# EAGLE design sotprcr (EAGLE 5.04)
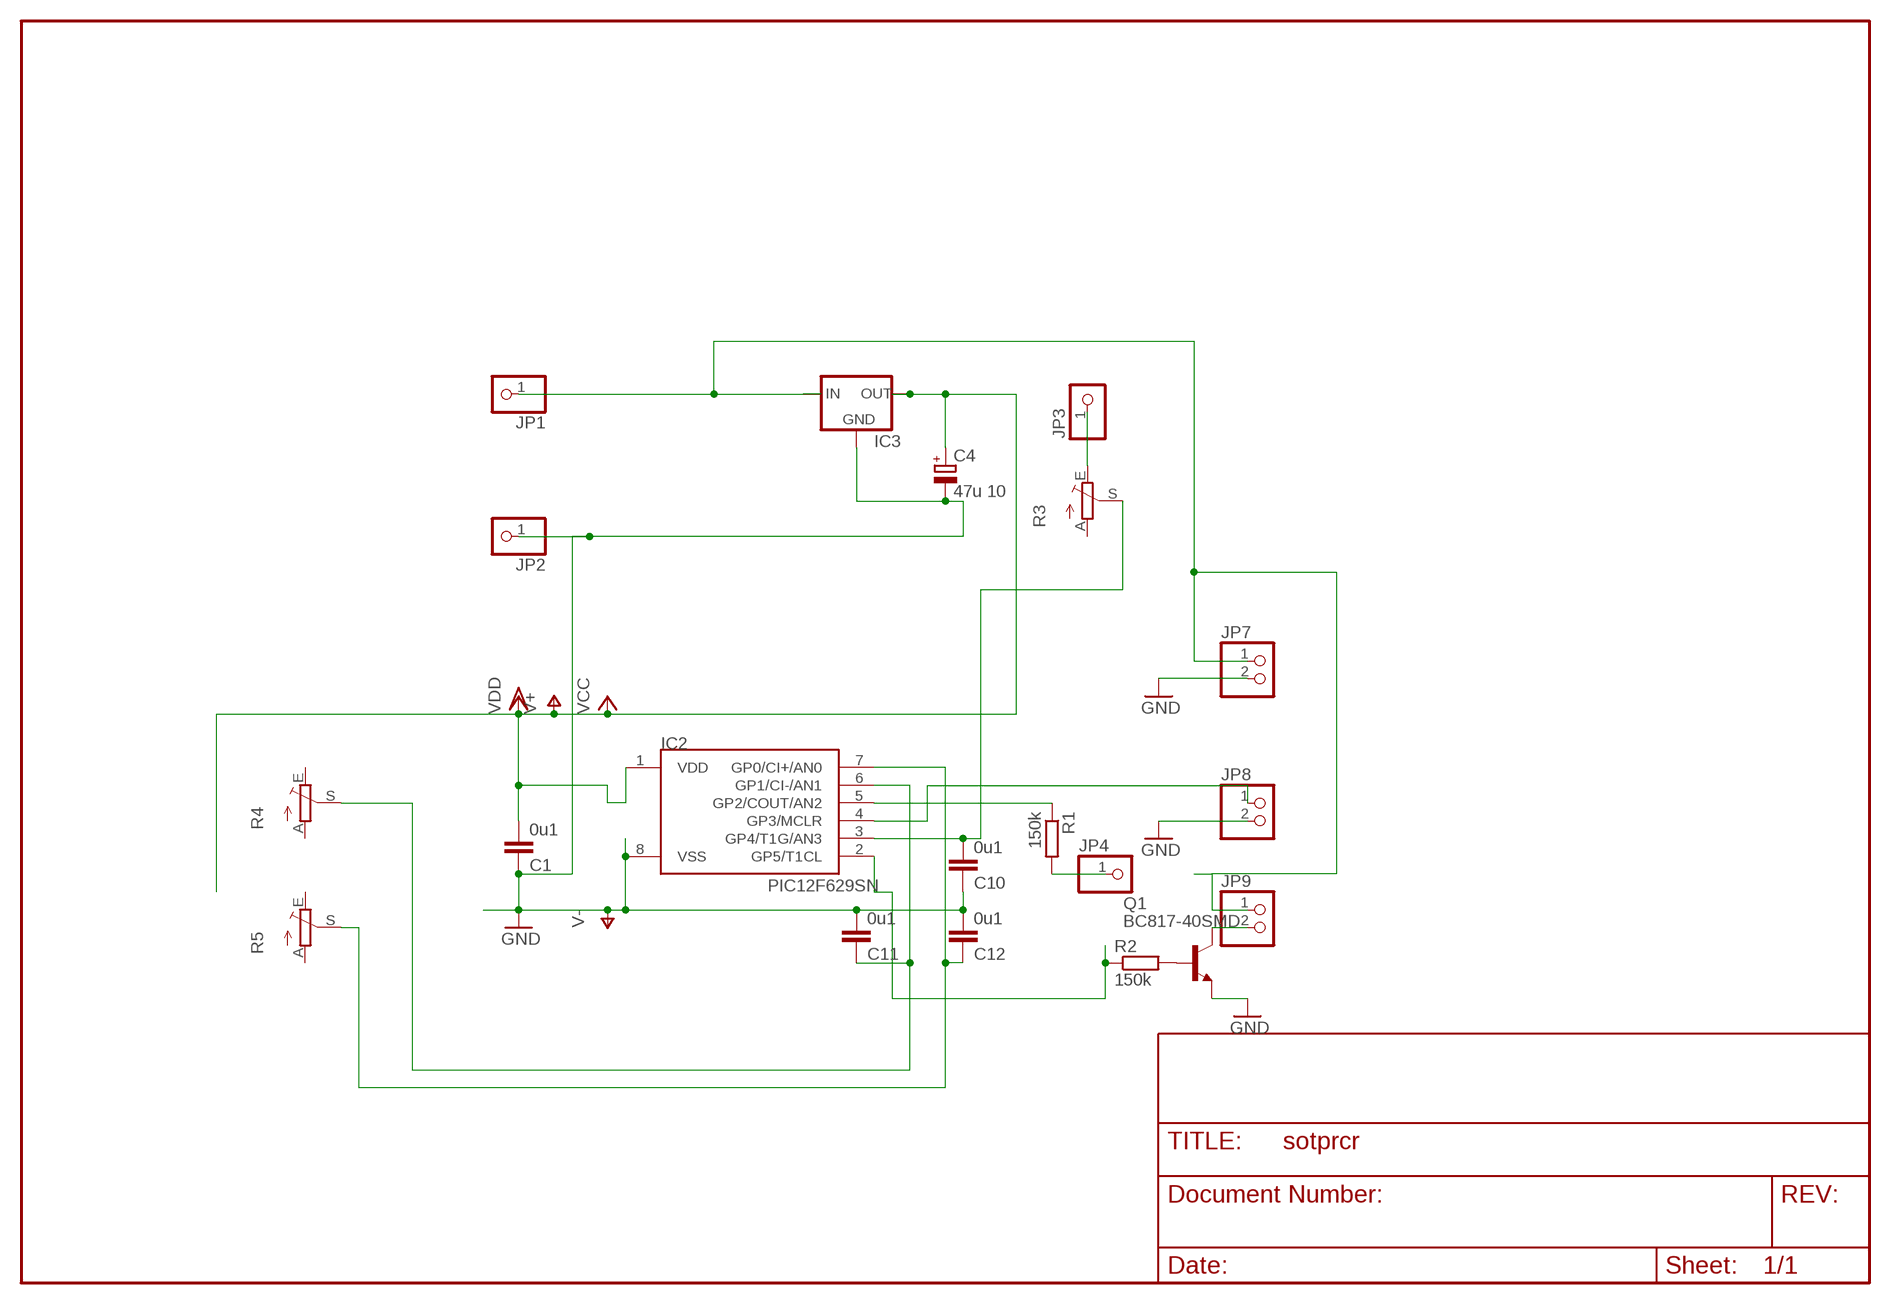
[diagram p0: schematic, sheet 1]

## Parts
C1  0u1  C-EUC1206  [C1206]
C4  47u 10  CPOL-EUE2.5-6  [E2,5-6]
C10  0u1  C-EUC1206  [C1206]
C11  0u1  C-EUC1206  [C1206]
C12  0u1  C-EUC1206  [C1206]
IC2  PIC12F629SN  [SO-08]
IC3  78LXX  [78LXX]
JP1  PINHD-1X1  [1X01]
JP2  PINHD-1X1  [1X01]
JP3  PINHD-1X1  [1X01]
JP4  PINHD-1X1  [1X01]
JP7  PINHD-1X2  [1X02]
JP8  PINHD-1X2  [1X02]
JP9  PINHD-1X2  [1X02]
Q1  BC817-40SMD  [SOT23-BEC]
R1  150k  R-EU_R0805  [R0805]
R2  150k  R-EU_R1206  [R1206]
R3  TRIM_EU-CA6V  [CA6V]
R4  TRIM_EU-CA6V  [CA6V]
R5  TRIM_EU-CA6V  [CA6V]

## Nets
GND: C1.1 C4.- C10.1 C11.2 C12.2 IC2.8(VSS) IC3.GND JP2.1 JP7.2 JP8.2 Q1.E ; supply symbol labelled V-
N$1: JP3.1 R3.E
N$2: JP4.1 R1.2
N$3: IC2.4(GP3/MCLR) JP8.1
N$5: IC2.5(GP2/COUT/AN2) R1.1
N$8: IC2.2(GP5/T1CL) R2.1
N$9: Q1.B R2.2
N$10: JP9.2 Q1.C
N$12: C10.2 IC2.3(GP4/T1G/AN3) R3.S
N$13: C12.1 IC2.7(GP0/CI+/AN0) R5.S
N$15: C11.1 IC2.6(GP1/CI-/AN1) R4.S
N$20: IC3.IN JP1.1 JP7.1 JP9.1
V+: C1.2 C4.+ IC2.1(VDD) IC3.OUT ; supply symbol labelled VCC, VDD
Unconnected: R3.A R4.A R4.E R5.A R5.E

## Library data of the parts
C1 C10-C12 = rcl:C-EU: CAPACITOR, European symbol
C4 = rcl:CPOL-EU: POLARIZED CAPACITOR, European symbol
IC2 = microchip-3:PIC12F6*: uPC nW 1k Program Flash memory 2x Timer Comparator 10b A/D converter/ 4xIN
IC3 = v-reg:78LXX: VOLTAGE REGULATOR
JP1-JP4 = pinhead:PINHD-1X1: PIN HEADER
JP7-JP9 = pinhead:PINHD-1X2: PIN HEADER
Q1 = transistor-npn:BC817*: NPN Transistor
R1 R2 = rcl:R-EU_: RESISTOR, European symbol
R3-R5 = pot:TRIM_EU-: POTENTIOMETER

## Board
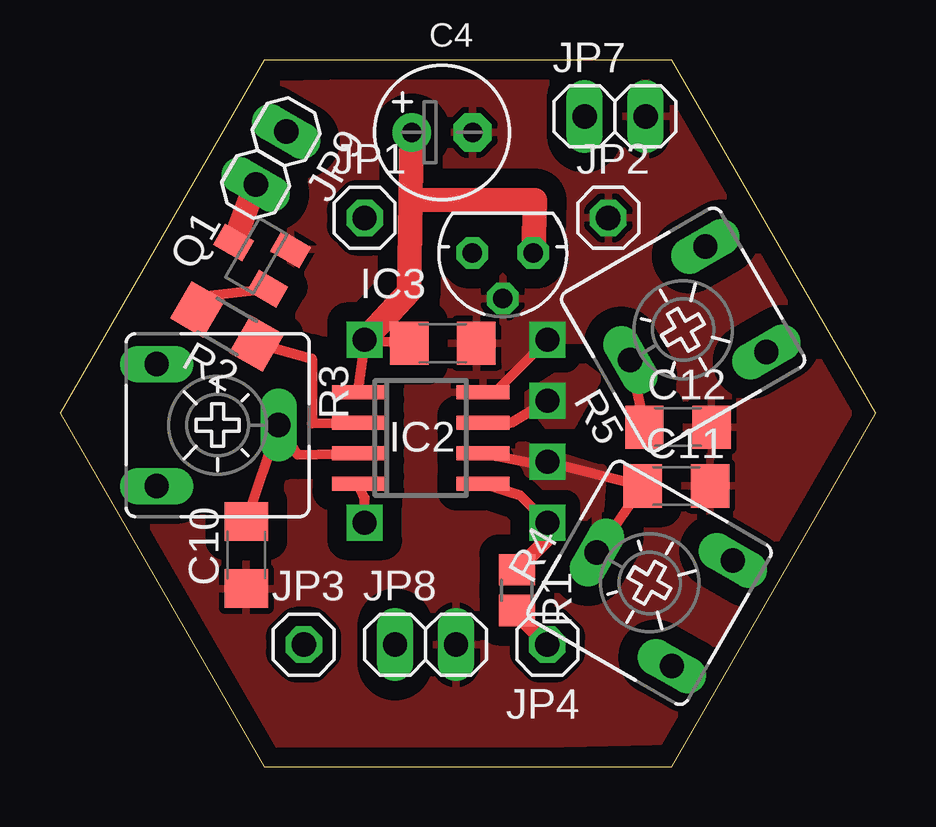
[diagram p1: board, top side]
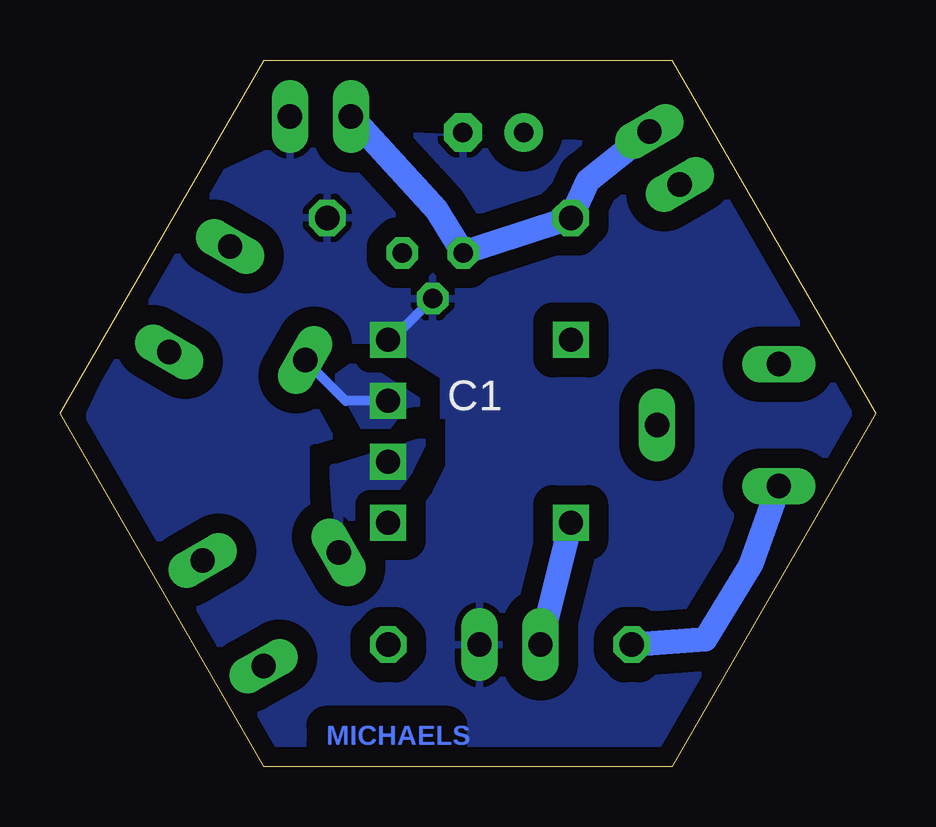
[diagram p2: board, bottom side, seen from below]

Size 34 x 29.44 mm. Coordinates in mm from the lower left corner, seen from the top.
Outline: 8.5,0 25.5,0 34,14.72 25.5,29.44 8.5,29.44 0,14.72 8.5,0
Copper layers (1*16): Top 0.035mm / dielectric 1.5mm / Bottom 0.035mm
Design rules "default *": minimum track width 10mil, minimum drill 24mil, track to track 8mil, track to pad 8mil, pad to pad 8mil, via to via 8mil, smd to smd 8mil, copper to edge 10mil, drill to drill 8mil, minimum pad ring 10mil, minimum via ring 8mil, stop-mask expansion 4mil, vias tented up to drill 0mil, thermal gap 10mil

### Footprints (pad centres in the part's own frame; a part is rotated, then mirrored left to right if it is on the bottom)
C1206 = smd 1.6 x 1.8: 1 -1.4,0; 2 1.4,0
E2,5-6 = drill 0.813 pad 1.6 round: + -1.27,0 | drill 0.813 pad 1.6 octagon: - 1.27,0
SO-08 = smd 0.6 x 2.2: 1 -1.905,-2.6; 2 -0.635,-2.6; 3 0.635,-2.6; 4 1.905,-2.6; 5 1.905,2.6; 6 0.635,2.6; 7 -0.635,2.6; 8 -1.905,2.6
78LXX = drill 0.813 octagon: GND 0,1.905; IN 1.27,0; OUT -1.27,0
1X01 = drill 1.016 octagon: 1 0,0
1X02 = drill 1.016 long: 1 -1.27,0; 2 1.27,0
SOT23-BEC = smd 1 x 1.4: B -0.95,-1.1; C 0,1.1; E 0.95,-1.1
R0805 = smd 1.3 x 1.5: 1 -0.85,0; 2 0.85,0
R1206 = smd 1.6 x 1.803: 1 -1.422,0; 2 1.422,0
CA6V = drill 1.016 long: A -2.54,-2.54; E 2.54,-2.54; S 0,2.54

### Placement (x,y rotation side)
C1  15.96,17.64 180 top
C4  15.93,26.42 0 top
C10  7.77,8.81 90 top
C11  25.7,11.69 0 top
C12  25.76,14.14 0 top
IC2  15.04,13.69 270 top
IC3  18.46,21.4 180 top
JP1  12.7,22.86 0 top
JP2  22.86,22.86 0 top
JP3  10.16,5.08 0 top
JP4  20.32,5.08 180 top
JP7  23.14,27.09 0 top
JP8  15.24,5.08 0 top
JP9  8.79,25.36 240 top
Q1  8.19,21.28 60 top
R1  19.05,7.35 270 top
R2  6.97,18.34 150 top
R3  6.57,14.23 270 top
R4  24.58,7.65 60 top
R5  25.98,18.2 120 top

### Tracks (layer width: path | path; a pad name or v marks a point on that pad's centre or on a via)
GND  (via drill 1)
  Top 0.406: IC2.8 18.24,15.7 v20.32,17.78
  Bottom 0.406: v20.32,17.78 20.18,17.78 IC3.GND
  pour Top (isolate 0.813, rank 4): 25.05,28.74 33.52,14.83 25.59,1.05 7.24,0.65 -0.28,14.57 9.11,28.44
  pour Bottom (isolate 0.813, rank 4): 25.09,0.65 6.94,0.85 -0.63,14.71 7.44,25.75 23.4,26.48 28.25,24.24 33.14,13.91
N$1
  Bottom 1.016: R3.E 5.2,8.4 7.1,5.3 JP3.1
N$2
  Top 0.61: R1.2 19.05,6.35 JP4.1
N$3  (via drill 1)
  Top 0.406: IC2.4 12.7,11.19 v12.7,10.16
  Bottom 1.016: JP8.1 v12.7,10.16
N$5  (via drill 1)
  Top 0.406: IC2.5 19.19,11.29 v20.32,10.16
  Top 0.61: v20.32,10.16 20.32,9.47 R1.1
N$8
  Top 0.406: R2.1 10.5,17 10.5,14.3 IC2.2
N$9
  Top 0.406: Q1.B 5.9,19.6 R2.2
N$10
  Top 1.016: Q1.C JP9.2
N$12
  Top 0.406: IC2.3 9.9,13 R3.S C10.2
N$13  (via drill 1)
  Top 0.406: IC2.7 18.81,14.33 v20.32,15.24 | R5.S C12.1
  Bottom 0.406: v20.32,15.24 22.08,15.24 R5.S
  pour Top (isolate 0.61): 19.7,15.1 20.9,13.5 22.4,16.2 21.6,16.8 19.1,15.2
  pour Bottom (isolate 0.61): 19.7,15.1 20.9,13.5 22.4,16.2 21.6,16.8 19.1,15.2
N$15  (via drill 1)
  Top 0.406: IC2.6 20.18,12.56 v20.32,12.7 C11.1 R4.S
  pour Top (isolate 0.61, rank 2): 18.9,13.5 22.4,12.4 22.6,12.4 22.4,9.8 21.7,9.4 19.5,12.3
  pour Bottom (isolate 0.61, rank 2): 18.9,13.5 22.4,12.4 22.6,12.4 22.4,9.8 21.7,9.4 19.5,12.3
N$20
  Bottom 1.016: JP7.1 18.3,23.2 IC3.IN JP1.1 12,24.4 JP9.1
V+  (via drill 1)
  Top 0.406: IC2.1 12.7,17.54 v12.7,17.78 C1.2
  Top 1.016: v12.7,17.78 14.56,19.78 14.62,23.61 | 14.62,23.61 C4.+ | IC3.OUT 19.8,23.6 14.62,23.61

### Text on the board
Bottom: MICHAELS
